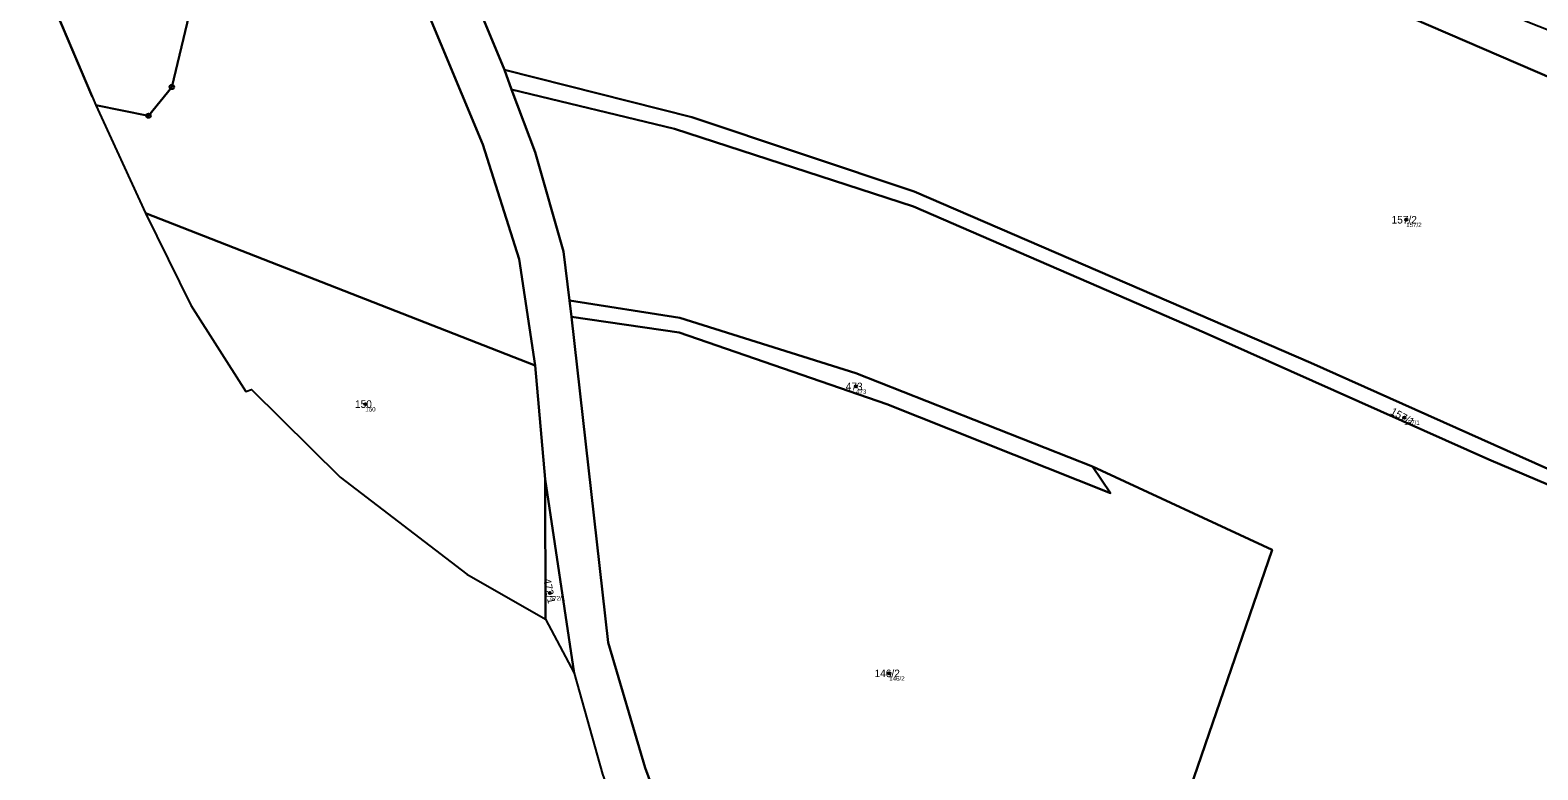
# Model space of a CAD drawing. Extents: x -700238 to -698499, y -1070626 to -1068006.
# Drawn here: x -700154.3 to -699815.7, y -1068498.7 to -1068332.5 of the extents above; entities that cross this region are included whole.
import ezdxf

# ---------------------------------------------------------------- set-up
doc = ezdxf.new("R2010")
doc.units = 0
for name, color, linetype in [('Definiční body', 7, 'Continuous'), ('Hranice parcel', 7, 'Continuous'), ('Parcelní čísla', 7, 'Continuous'), ('Polygon ku', 7, 'Continuous'), ('Polygon parcely', 7, 'Continuous'), ('Značky bodu BP', 7, 'Continuous')]:
    doc.layers.add(name, color=color, linetype=linetype)

msp = doc.modelspace()

# ---------------------------------------------------------------- linework, layer by layer
at = {"layer": 'Definiční body'}
for centre in [(-699845.24, -1068375.11994), (-699968.82, -1068412.55994), (-700079.04, -1068416.52994), (-699845.67, -1068419.54994), (-700037.61, -1068458.93994), (-699961.37, -1068476.99994)]:
    msp.add_circle(centre, 0.25, dxfattribs=at)
at = {"layer": 'Hranice parcel'}
for p, q in [((-700140.37, -1068347.45), (-700154.33, -1068314.6)), ((-700046.18, -1068345.86), (-700047.78, -1068341.46)), ((-700140.37, -1068347.45), (-700139.55, -1068349.38)), ((-700139.55, -1068349.38), (-700128.39, -1068373.62)), ((-700128.39, -1068373.62), (-700040.88, -1068407.88)), ((-700033.18, -1068393.26), (-700032.77, -1068396.95)), ((-700040.88, -1068407.88), (-700038.62, -1068433.4)), ((-700032.11, -1068476.97), (-700038.62, -1068433.4)), ((-700038.62, -1068433.4), (-700038.61, -1068464.81)), ((-700038.61, -1068464.81), (-700032.11, -1068476.97))]:
    msp.add_line(p, q, dxfattribs=at)
for points in [[(-700047.78, -1068341.46), (-700079.51, -1068265.19), (-700089.79, -1068219.21)], [(-699627.99, -1068411.98), (-699659.02, -1068402.7), (-699710.69, -1068385.66), (-699740.56, -1068374.38), (-699875.66, -1068316.05), (-699927.93, -1068294.45), (-700000.63, -1068259.75), (-700062.96, -1068229.76), (-700089.79, -1068219.21)], [(-700095.19, -1068243.17), (-700097.88, -1068242.45), (-700122.52, -1068345.31), (-700127.75, -1068351.76), (-700139.55, -1068349.38)], [(-700040.88, -1068407.88), (-700044.5, -1068383.96), (-700052.63, -1068358.24), (-700085.32, -1068279.92), (-700095.19, -1068243.17)], [(-699655.97, -1068487.17), (-699746.59, -1068459.53), (-699790, -1068441.55), (-699866.66, -1068407.29), (-699955.8, -1068368.76), (-700005.69, -1068352.12), (-700047.78, -1068341.46)], [(-700046.18, -1068345.86), (-700040.87, -1068359.92), (-700034.51, -1068382.29), (-700033.18, -1068393.26)], [(-699657.18, -1068490.6), (-699745.37, -1068463.45), (-699826.68, -1068428.95), (-699890.63, -1068400.44), (-699955.93, -1068372.18), (-700009.61, -1068354.69), (-700046.18, -1068345.86)], [(-700128.39, -1068373.62), (-700118.25, -1068394.29), (-700105.87, -1068413.73)], [(-700033.18, -1068393.26), (-700008.42, -1068397.14), (-699968.89, -1068409.59), (-699915.7, -1068430.51)], [(-699915.7, -1068430.51), (-699911.65, -1068436.52), (-699961.88, -1068416.53), (-700008.52, -1068400.47), (-700032.77, -1068396.95)], [(-700032.77, -1068396.95), (-700024.51, -1068470.1), (-700016.2, -1068498.25), (-700009.96, -1068515.01), (-699998.59, -1068537.76), (-699993.45, -1068545.35)], [(-700105.87, -1068413.73), (-700104.64, -1068413.25), (-700084.73, -1068432.94), (-700056.23, -1068454.74), (-700038.61, -1068464.81)], [(-699915.7, -1068430.51), (-699875.35, -1068449.22), (-699911.29, -1068553.85)], [(-700032.11, -1068476.97), (-700025.78, -1068499.64), (-700016.98, -1068523.96)]]:
    msp.add_lwpolyline(points, dxfattribs=at)
at = {"layer": 'Polygon ku'}
msp.add_lwpolyline([(-700154.33, -1068314.6), (-700140.37, -1068347.45), (-700139.55, -1068349.38), (-700128.39, -1068373.62), (-700118.25, -1068394.29), (-700105.87, -1068413.73), (-700104.64, -1068413.25), (-700084.73, -1068432.94), (-700056.23, -1068454.74), (-700038.61, -1068464.81), (-700032.11, -1068476.97), (-700025.78, -1068499.64)], dxfattribs=at)
at = {"layer": 'Polygon parcely'}
for points in [[(-699708.94, -1068373.65), (-699817.93, -1068330.74), (-699901.99, -1068293.89), (-700054.94, -1068220), (-700092.18, -1068203.16), (-700089.79, -1068219.21), (-700062.96, -1068229.76), (-700000.63, -1068259.75), (-699927.93, -1068294.45), (-699875.66, -1068316.05), (-699740.56, -1068374.38), (-699710.69, -1068385.66), (-699659.02, -1068402.7), (-699627.99, -1068411.98), (-699623.95, -1068401.12)], [(-700000.63, -1068259.75), (-700062.96, -1068229.76), (-700089.79, -1068219.21), (-700079.51, -1068265.19), (-700047.78, -1068341.46), (-700005.69, -1068352.12), (-699955.8, -1068368.76), (-699866.66, -1068407.29), (-699790, -1068441.55), (-699746.59, -1068459.53), (-699655.97, -1068487.17), (-699627.99, -1068411.98), (-699659.02, -1068402.7), (-699710.69, -1068385.66), (-699740.56, -1068374.38), (-699875.66, -1068316.05), (-699927.93, -1068294.45)], [(-700044.5, -1068383.96), (-700052.63, -1068358.24), (-700085.32, -1068279.92), (-700095.19, -1068243.17), (-700097.88, -1068242.45), (-700122.52, -1068345.31), (-700127.75, -1068351.76), (-700139.55, -1068349.38), (-700128.39, -1068373.62), (-700040.88, -1068407.88)], [(-700047.78, -1068341.46), (-700046.18, -1068345.86), (-700009.61, -1068354.69), (-699955.93, -1068372.18), (-699890.63, -1068400.44), (-699826.68, -1068428.95), (-699745.37, -1068463.45), (-699657.18, -1068490.6), (-699655.97, -1068487.17), (-699746.59, -1068459.53), (-699790, -1068441.55), (-699866.66, -1068407.29), (-699955.8, -1068368.76), (-700005.69, -1068352.12)], [(-699955.93, -1068372.18), (-700009.61, -1068354.69), (-700046.18, -1068345.86), (-700040.87, -1068359.92), (-700034.51, -1068382.29), (-700033.18, -1068393.26), (-700008.42, -1068397.14), (-699968.89, -1068409.59), (-699915.7, -1068430.51), (-699875.35, -1068449.22), (-699911.29, -1068553.85), (-699895.28, -1068555.81), (-699839.16, -1068564.86), (-699779.49, -1068577.34), (-699695.89, -1068598.19), (-699684.13, -1068602.07), (-699680.08, -1068567.69), (-699671.14, -1068527.69), (-699657.18, -1068490.6), (-699745.37, -1068463.45), (-699826.68, -1068428.95), (-699890.63, -1068400.44)], [(-700105.87, -1068413.73), (-700104.64, -1068413.25), (-700084.73, -1068432.94), (-700056.23, -1068454.74), (-700038.61, -1068464.81), (-700038.62, -1068433.4), (-700040.88, -1068407.88), (-700128.39, -1068373.62), (-700118.25, -1068394.29)], [(-700033.18, -1068393.26), (-700032.77, -1068396.95), (-700008.52, -1068400.47), (-699961.88, -1068416.53), (-699911.65, -1068436.52), (-699915.7, -1068430.51), (-699968.89, -1068409.59), (-700008.42, -1068397.14)], [(-700032.77, -1068396.95), (-700024.51, -1068470.1), (-700016.2, -1068498.25), (-700009.96, -1068515.01), (-699998.59, -1068537.76), (-699993.45, -1068545.35), (-699911.29, -1068553.85), (-699875.35, -1068449.22), (-699915.7, -1068430.51), (-699911.65, -1068436.52), (-699961.88, -1068416.53), (-700008.52, -1068400.47)], [(-700038.62, -1068433.4), (-700038.61, -1068464.81), (-700032.11, -1068476.97)]]:
    msp.add_lwpolyline(points, close=True, dxfattribs=at)
for points in [[(-700154.33, -1068314.6), (-700140.37, -1068347.45), (-700139.55, -1068349.38), (-700127.75, -1068351.76), (-700122.52, -1068345.31), (-700097.88, -1068242.45)], [(-700009.96, -1068515.01), (-700016.2, -1068498.25), (-700024.51, -1068470.1), (-700032.77, -1068396.95), (-700033.18, -1068393.26), (-700034.51, -1068382.29), (-700040.87, -1068359.92), (-700046.18, -1068345.86), (-700047.78, -1068341.46), (-700079.51, -1068265.19)], [(-700085.32, -1068279.92), (-700052.63, -1068358.24), (-700044.5, -1068383.96), (-700040.88, -1068407.88), (-700038.62, -1068433.4), (-700032.11, -1068476.97), (-700025.78, -1068499.64)]]:
    msp.add_lwpolyline(points, dxfattribs=at)
at = {"layer": 'Značky bodu BP'}
for centre, radius in [((-700122.52, -1068345.30988), 0.5), ((-700122.52, -1068345.30988), 0.0303), ((-700127.75, -1068351.75988), 0.5), ((-700127.75, -1068351.75988), 0.0303)]:
    msp.add_circle(centre, radius, dxfattribs=at)

# ---------------------------------------------------------------- texts
at = {"layer": 'Definiční body'}
for s, p in [('157/2', (-699845.24, -1068376.776)), ('473', (-699968.82, -1068414.216)), ('150', (-700079.04, -1068418.186)), ('157/1', (-699845.67, -1068421.206)), ('472/1', (-700037.61, -1068460.596)), ('146/2', (-699961.37, -1068478.656))]:
    msp.add_text(s, height=0.999996, dxfattribs=at).set_placement(p)
at = {"layer": 'Parcelní čísla'}
for s, p in [('157/2', (-699848.538, -1068375.97)), ('473', (-699971.145, -1068413.41)), ('150', (-700081.365, -1068417.38)), ('146/2', (-699964.668, -1068477.85))]:
    msp.add_text(s, height=1.699998, dxfattribs=at).set_placement(p)
for s, rotation, p in [('157/1', 331, (-699848.967, -1068418.694)), ('472/1', 281, (-700039.073, -1068455.864))]:
    msp.add_text(s, height=1.699998, rotation=rotation, dxfattribs=at).set_placement(p)

doc.saveas('drawing.dxf')
